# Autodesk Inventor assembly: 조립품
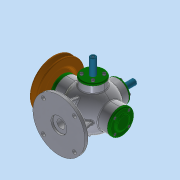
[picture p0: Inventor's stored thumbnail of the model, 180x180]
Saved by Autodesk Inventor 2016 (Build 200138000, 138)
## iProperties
Created: 2019-11
Part Number: 조립품
Material: 일반
Document SubType Name: Assembly
Designer: user
Mass: 3778.22 g
Surface Area: 2410.86 cm^2
Volume: 904.614 cm^3
Density: 4.17661 g/cm^3
Author: user
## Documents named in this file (17)
- C:\Users\user\Desktop\391120V1009\조립품.iam
- C:\Users\user\Desktop\391120V1009\V-벨트풀리.ipt
- C:\Users\user\Desktop\391120V1009\너트 M8x1.ipt
- C:\Users\user\Desktop\391120V1009\뒤커버.ipt
- C:\Users\user\Desktop\391120V1009\베어링 6202.ipt
- C:\Users\user\Desktop\391120V1009\본체.ipt
- C:\Users\user\Desktop\391120V1009\본체커버.ipt
- C:\Users\user\Desktop\391120V1009\볼트 M4.ipt
- C:\Users\user\Desktop\391120V1009\스프링1.ipt
- C:\Users\user\Desktop\391120V1009\스프링2.ipt
- C:\Users\user\Desktop\391120V1009\슬라이드 커버.ipt
- C:\Users\user\Desktop\391120V1009\슬라이드.ipt
- C:\Users\user\Desktop\391120V1009\앞커버.ipt
- C:\Users\user\Desktop\391120V1009\오일 실.ipt
- C:\Users\user\Desktop\391120V1009\와셔 8x17.ipt
- C:\Users\user\Desktop\391120V1009\축.ipt
- C:\Users\user\Desktop\391120V1009\키 4x4.ipt
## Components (1 placed, 1 different names)
1. V-벨트풀리:1 — 플러쉬:1
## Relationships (1: Flush 1)
- 플러쉬:1 [Flush]: V-벨트풀리:1
